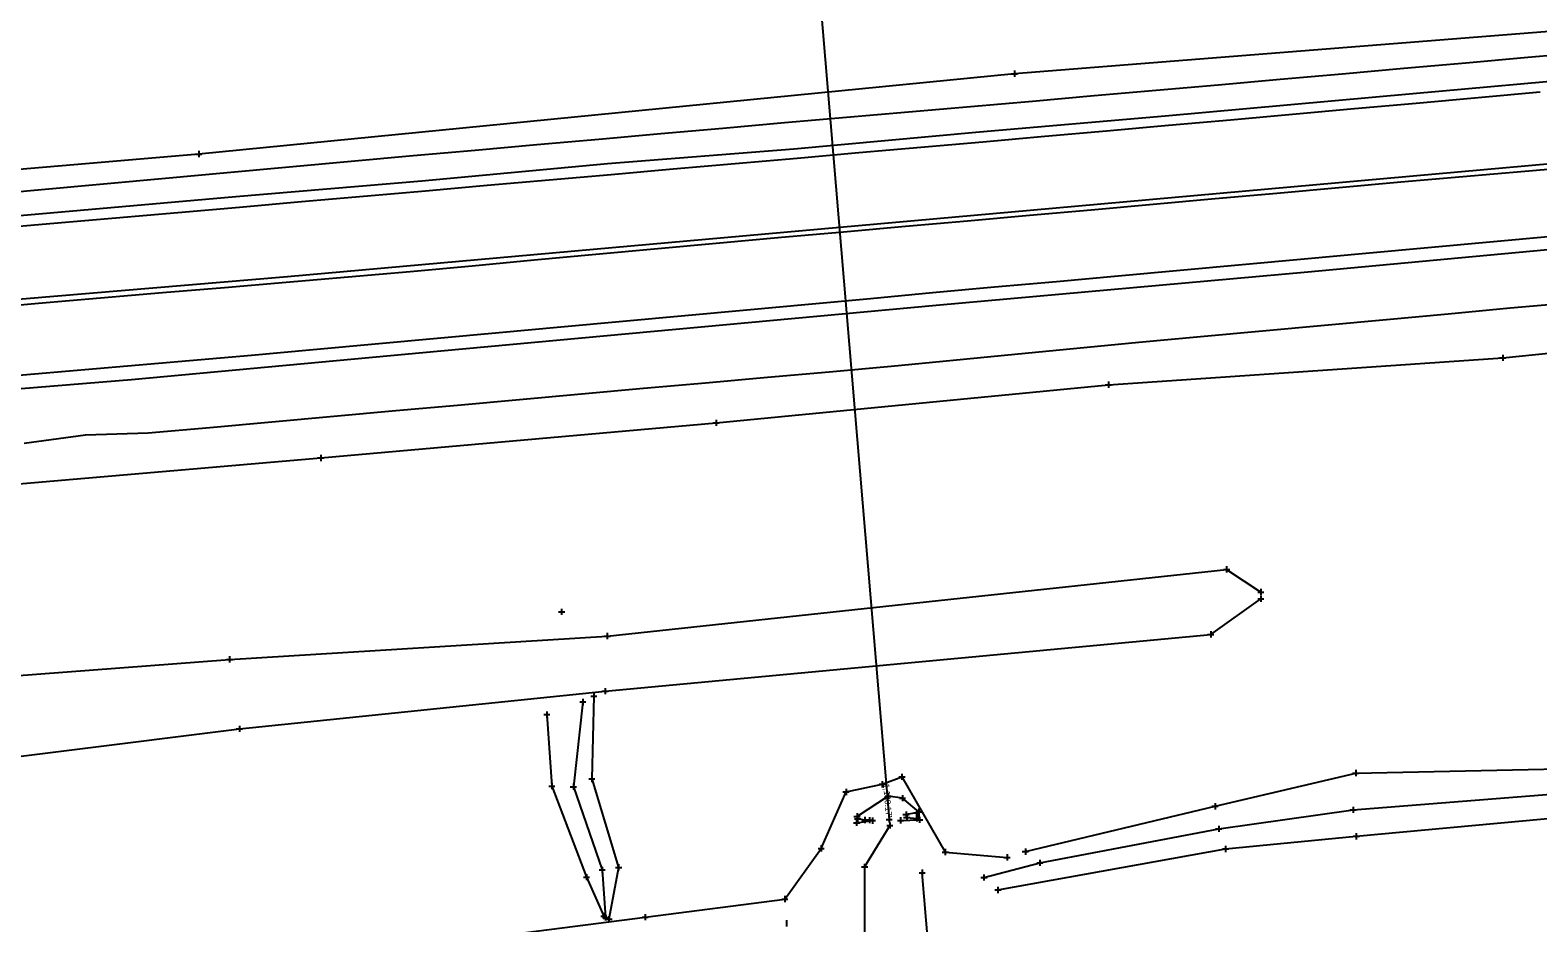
# Model space of a CAD drawing. Extents: x 207090 to 277928, y 600777 to 621109.
# Drawn here: x 261434.3 to 261676.8, y 612064.8 to 612208.4 of the extents above; entities that cross this region are included whole.
import ezdxf

# ---------------------------------------------------------------- set-up
doc = ezdxf.new("R2010")
doc.units = 0
for name, color, linetype in [('ATDIMS', 7, 'Continuous'), ('DR_X_Ditch', 7, 'Continuous'), ('DR_X_Headwall', 7, 'Continuous'), ('DR_X_Storm_Sewer', 7, 'Continuous'), ('HY_X_Water_Edge', 7, 'Continuous'), ('PM_P_Edge_Line', 7, 'Continuous'), ('PM_P_Stop_Line', 7, 'Continuous'), ('PM_X_Edge_Line', 7, 'Continuous'), ('PM_X_Lane_Line', 7, 'Continuous'), ('PV_X_COP', 7, 'Continuous'), ('PV_X_EOP', 7, 'Continuous'), ('PV_X_Shoulder_Rumble_Strip', 7, 'Continuous'), ('SC_ProfileRun2', 7, 'Continuous'), ('SV_X_Break_Lines', 7, 'Continuous'), ('SV_X_Toe_of_Slope', 7, 'Continuous')]:
    doc.layers.add(name, color=color, linetype=linetype)

msp = doc.modelspace()

# ---------------------------------------------------------------- linework, layer by layer
at = {"layer": 'DR_X_Ditch'}
for points in [[(261587.67, 612072.1), (261596.66, 612074.46), (261625.44, 612079.93), (261647.05, 612082.98), (261707.29, 612087.78), (261756.51, 612096.79), (261822.22, 612111.69), (261862.35, 612121.75), (261869.62, 612124.52), (261870.17, 612126.4)], [(261523.17, 612100.35), (261521.64, 612086.71), (261526.27, 612073.31), (261526.81, 612065.66)], [(261572.54, 612080.46), (261568.48, 612073.82)], [(261568.48, 612073.82), (261568.59, 612020.15), (261578.54, 611927.79), (261603.98, 611904.17), (261618.07, 611868.23), (261663.61, 611784.94), (261667.47, 611772.86)]]:
    msp.add_lwpolyline(points, dxfattribs=at)
at = {"layer": 'DR_X_Headwall'}
for points in [[(261575.25, 612081.77), (261576.9, 612081.6), (261576.88, 612082.48), (261575.15, 612082.21)], [(261569.28, 612081.32), (261568.52, 612081.35), (261567.36, 612081.53)]]:
    msp.add_lwpolyline(points, dxfattribs=at)
at = {"layer": 'DR_X_Storm_Sewer'}
msp.add_line((261547.33, 612379.42), (261572.44, 612081.43), dxfattribs=at)
at = {"layer": 'HY_X_Water_Edge'}
msp.add_lwpolyline([(261668.89, 611786.74), (261623.52, 611871.92), (261599.31, 611926.43), (261586.65, 611981.1), (261582.23, 612019.52), (261577.74, 612072.86)], dxfattribs=at)
at = {"layer": 'PM_P_Edge_Line'}
for points in [[(262691.17, 612299.71), (262558.11, 612286.52), (262430.17, 612277.43), (262301.59, 612265.47), (262139.8, 612250.04), (262013.02, 612239.05), (261851.77, 612225.58), (261721.98, 612211.64), (261592.59, 612201.42), (261461.4, 612188.5), (261326.91, 612177), (261204.29, 612172.31), (261203.79, 612197.21), (261194.23, 612211.46)], [(261166.19, 612112.27), (261229.12, 612117.55), (261292.26, 612122.22), (261355.79, 612127.7), (261417.51, 612134.17), (261481.01, 612139.6), (261544.6, 612145.26), (261607.7, 612151.39), (261671.11, 612155.71), (261734.7, 612162.2), (261800.15, 612167.35), (261866.92, 612170.66), (261934.78, 612175.92), (261991.88, 612185.8), (262015.18, 612187.39), (262056.96, 612191.38), (262138.36, 612199.04), (262221.59, 612205.24), (262304.08, 612210.43), (262405.7, 612222.35)], [(261594.35, 612076.26), (261624.84, 612083.55), (261647.48, 612088.9), (261707.89, 612090.17), (261755.27, 612098.62), (261821.94, 612116.68), (261862.35, 612125.03), (261875.37, 612130.72)], [(261589.93, 612070.09), (261626.55, 612076.69), (261647.57, 612078.73), (261708.01, 612084.31), (261757.15, 612093.18), (261825.61, 612102.33), (261823.02, 612108.36), (261863.27, 612119.66), (261875.97, 612119.24), (261875.86, 612129.94)], [(261282.94, 612074.88), (261303.34, 612074.99), (261352, 612080.99), (261411.83, 612088.97), (261467.93, 612096.02), (261526.73, 612102.07), (261624.15, 612111.22), (261632.22, 612116.93)], [(261524.93, 612101.26), (261524.61, 612087.96), (261528.92, 612073.73), (261527.36, 612065.39)], [(261517.37, 612098.3), (261518.17, 612086.81), (261523.75, 612072.15), (261526.54, 612065.89)]]:
    msp.add_lwpolyline(points, dxfattribs=at)
at = {"layer": 'PM_P_Stop_Line'}
for p, q in [((261592.09, 612201.42), (261593.09, 612201.42)), ((261592.59, 612201.92), (261592.59, 612200.92)), ((261592.59, 612201.42), (261592.59, 612201.42)), ((261460.9, 612188.5), (261461.9, 612188.5)), ((261461.4, 612189), (261461.4, 612188)), ((261461.4, 612188.5), (261461.4, 612188.5)), ((261670.61, 612155.71), (261671.61, 612155.71)), ((261671.11, 612156.21), (261671.11, 612155.21)), ((261671.11, 612155.71), (261671.11, 612155.71)), ((261607.2, 612151.39), (261608.2, 612151.39)), ((261607.7, 612151.89), (261607.7, 612150.89)), ((261607.7, 612151.39), (261607.7, 612151.39)), ((261544.1, 612145.26), (261545.1, 612145.26)), ((261544.6, 612145.76), (261544.6, 612144.76)), ((261544.6, 612145.26), (261544.6, 612145.26)), ((261481.01, 612140.1), (261481.01, 612139.1)), ((261480.51, 612139.6), (261481.51, 612139.6)), ((261481.01, 612139.6), (261481.01, 612139.6)), ((261626.21, 612121.67), (261627.21, 612121.67)), ((261626.71, 612122.17), (261626.71, 612121.17)), ((261626.71, 612121.67), (261626.71, 612121.67)), ((261632.21, 612118.52), (261632.21, 612117.52)), ((261631.71, 612118.02), (261632.71, 612118.02)), ((261631.72, 612116.93), (261632.72, 612116.93)), ((261632.21, 612118.02), (261632.21, 612118.02)), ((261632.22, 612117.43), (261632.22, 612116.43)), ((261632.22, 612116.93), (261632.22, 612116.93)), ((261526.59, 612110.95), (261527.59, 612110.95)), ((261527.09, 612111.45), (261527.09, 612110.45)), ((261527.09, 612110.95), (261527.09, 612110.95)), ((261623.65, 612111.22), (261624.65, 612111.22)), ((261624.15, 612111.72), (261624.15, 612110.72)), ((261624.15, 612111.22), (261624.15, 612111.22)), ((261465.85, 612107.2), (261466.85, 612107.2)), ((261466.35, 612107.7), (261466.35, 612106.7)), ((261466.35, 612107.2), (261466.35, 612107.2)), ((261524.43, 612101.26), (261525.43, 612101.26)), ((261524.93, 612101.76), (261524.93, 612100.76)), ((261524.93, 612101.26), (261524.93, 612101.26)), ((261526.23, 612102.07), (261527.23, 612102.07)), ((261526.73, 612102.57), (261526.73, 612101.57)), ((261526.73, 612102.07), (261526.73, 612102.07)), ((261517.37, 612098.8), (261517.37, 612097.8)), ((261522.67, 612100.35), (261523.67, 612100.35)), ((261523.17, 612100.85), (261523.17, 612099.85)), ((261523.17, 612100.35), (261523.17, 612100.35)), ((261467.93, 612096.52), (261467.93, 612095.52)), ((261516.87, 612098.3), (261517.87, 612098.3)), ((261517.37, 612098.3), (261517.37, 612098.3)), ((261467.43, 612096.02), (261468.43, 612096.02)), ((261467.93, 612096.02), (261467.93, 612096.02)), ((261647.48, 612089.4), (261647.48, 612088.4)), ((261517.67, 612086.81), (261518.67, 612086.81)), ((261518.17, 612087.31), (261518.17, 612086.31)), ((261518.17, 612086.81), (261518.17, 612086.81)), ((261521.14, 612086.71), (261522.14, 612086.71)), ((261521.64, 612087.21), (261521.64, 612086.21)), ((261521.64, 612086.71), (261521.64, 612086.71)), ((261524.11, 612087.96), (261525.11, 612087.96)), ((261524.61, 612088.46), (261524.61, 612087.46)), ((261524.61, 612087.96), (261524.61, 612087.96)), ((261570.81, 612087.09), (261571.81, 612087.09)), ((261571.31, 612087.59), (261571.31, 612086.59)), ((261571.31, 612087.09), (261571.31, 612087.09)), ((261573.99, 612088.3), (261574.99, 612088.3)), ((261574.49, 612088.8), (261574.49, 612087.8)), ((261574.49, 612088.3), (261574.49, 612088.3)), ((261646.98, 612088.9), (261647.98, 612088.9)), ((261647.48, 612088.9), (261647.48, 612088.9)), ((261565, 612085.86), (261566, 612085.86)), ((261565.5, 612086.36), (261565.5, 612085.36)), ((261565.5, 612085.86), (261565.5, 612085.86)), ((261571.77, 612085.18), (261572.77, 612085.18)), ((261572.27, 612085.68), (261572.27, 612084.68)), ((261572.27, 612085.18), (261572.27, 612085.18)), ((261574.08, 612084.87), (261575.08, 612084.87)), ((261574.58, 612085.37), (261574.58, 612084.37)), ((261574.58, 612084.87), (261574.58, 612084.87)), ((261566.77, 612081.93), (261567.77, 612081.93)), ((261567.27, 612082.43), (261567.27, 612081.43)), ((261567.27, 612081.93), (261567.27, 612081.93)), ((261567.36, 612082.03), (261567.36, 612081.03)), ((261568.52, 612081.85), (261568.52, 612080.85)), ((261569.28, 612081.82), (261569.28, 612080.82)), ((261574.28, 612081.78), (261574.28, 612080.78)), ((261574.65, 612082.21), (261575.65, 612082.21)), ((261575.15, 612082.71), (261575.15, 612081.71)), ((261575.15, 612082.21), (261575.15, 612082.21)), ((261575.25, 612082.27), (261575.25, 612081.27)), ((261576.38, 612082.48), (261577.38, 612082.48)), ((261576.71, 612082.69), (261577.71, 612082.69)), ((261576.88, 612082.98), (261576.88, 612081.98)), ((261576.88, 612082.48), (261576.88, 612082.48)), ((261576.9, 612082.1), (261576.9, 612081.1)), ((261577.21, 612083.19), (261577.21, 612082.19)), ((261577.21, 612082.69), (261577.21, 612082.69)), ((261577.33, 612081.87), (261577.33, 612080.87)), ((261624.34, 612083.55), (261625.34, 612083.55)), ((261624.84, 612084.05), (261624.84, 612083.05)), ((261624.84, 612083.55), (261624.84, 612083.55)), ((261646.55, 612082.98), (261647.55, 612082.98)), ((261647.05, 612083.48), (261647.05, 612082.48)), ((261647.05, 612082.98), (261647.05, 612082.98)), ((261566.69, 612080.89), (261567.69, 612080.89)), ((261566.86, 612081.53), (261567.86, 612081.53)), ((261567.19, 612081.39), (261567.19, 612080.39)), ((261567.19, 612080.89), (261567.19, 612080.89)), ((261567.36, 612081.53), (261567.36, 612081.53)), ((261568.02, 612081.35), (261569.02, 612081.35)), ((261568.52, 612081.35), (261568.52, 612081.35)), ((261568.78, 612081.32), (261569.78, 612081.32)), ((261569.23, 612081.25), (261570.23, 612081.25)), ((261569.28, 612081.32), (261569.28, 612081.32)), ((261569.73, 612081.75), (261569.73, 612080.75)), ((261569.73, 612081.25), (261569.73, 612081.25)), ((261572.04, 612080.46), (261573.04, 612080.46)), ((261572.54, 612080.96), (261572.54, 612079.96)), ((261572.54, 612080.46), (261572.54, 612080.46)), ((261573.78, 612081.28), (261574.78, 612081.28)), ((261574.28, 612081.28), (261574.28, 612081.28)), ((261574.75, 612081.77), (261575.75, 612081.77)), ((261575.25, 612081.77), (261575.25, 612081.77)), ((261576.4, 612081.6), (261577.4, 612081.6)), ((261576.83, 612081.37), (261577.83, 612081.37)), ((261576.9, 612081.6), (261576.9, 612081.6)), ((261577.33, 612081.37), (261577.33, 612081.37)), ((261624.94, 612079.93), (261625.94, 612079.93)), ((261625.44, 612080.43), (261625.44, 612079.43)), ((261625.44, 612079.93), (261625.44, 612079.93)), ((261561.49, 612077.28), (261561.49, 612076.28)), ((261626.55, 612077.19), (261626.55, 612076.19)), ((261647.07, 612078.73), (261648.07, 612078.73)), ((261647.57, 612079.23), (261647.57, 612078.22)), ((261647.57, 612078.73), (261647.57, 612078.73)), ((261560.99, 612076.78), (261561.99, 612076.78)), ((261561.49, 612076.78), (261561.49, 612076.78)), ((261580.96, 612076.19), (261581.96, 612076.19)), ((261581.46, 612076.69), (261581.46, 612075.69)), ((261581.46, 612076.19), (261581.46, 612076.19)), ((261590.92, 612075.34), (261591.92, 612075.34)), ((261591.42, 612075.84), (261591.42, 612074.84)), ((261591.42, 612075.34), (261591.42, 612075.34)), ((261593.85, 612076.26), (261594.85, 612076.26)), ((261594.35, 612076.76), (261594.35, 612075.76)), ((261594.35, 612076.26), (261594.35, 612076.26)), ((261596.66, 612074.96), (261596.66, 612073.96)), ((261626.05, 612076.69), (261627.05, 612076.69)), ((261626.55, 612076.69), (261626.55, 612076.69)), ((261523.25, 612072.15), (261524.25, 612072.15)), ((261523.75, 612072.65), (261523.75, 612071.65)), ((261523.75, 612072.15), (261523.75, 612072.15)), ((261525.77, 612073.31), (261526.77, 612073.31)), ((261526.27, 612073.81), (261526.27, 612072.81)), ((261526.27, 612073.31), (261526.27, 612073.31)), ((261528.42, 612073.73), (261529.42, 612073.73)), ((261528.92, 612074.23), (261528.92, 612073.23)), ((261528.92, 612073.73), (261528.92, 612073.73)), ((261567.98, 612073.82), (261568.98, 612073.82)), ((261568.48, 612074.32), (261568.48, 612073.32)), ((261568.48, 612073.82), (261568.48, 612073.82)), ((261577.24, 612072.86), (261578.24, 612072.86)), ((261577.74, 612073.36), (261577.74, 612072.36)), ((261577.74, 612072.86), (261577.74, 612072.86)), ((261587.17, 612072.1), (261588.17, 612072.1)), ((261587.67, 612072.6), (261587.67, 612071.6)), ((261587.67, 612072.1), (261587.67, 612072.1)), ((261596.16, 612074.46), (261597.16, 612074.46)), ((261596.66, 612074.46), (261596.66, 612074.46)), ((261589.43, 612070.09), (261590.43, 612070.09)), ((261589.93, 612070.59), (261589.93, 612069.59)), ((261589.93, 612070.09), (261589.93, 612070.09)), ((261555.15, 612068.63), (261556.15, 612068.63)), ((261555.65, 612069.13), (261555.65, 612068.13)), ((261555.65, 612068.63), (261555.65, 612068.63)), ((261526.04, 612065.89), (261527.04, 612065.89)), ((261526.31, 612065.66), (261527.31, 612065.66)), ((261526.54, 612066.39), (261526.54, 612065.39)), ((261526.54, 612065.89), (261526.54, 612065.89)), ((261526.81, 612066.16), (261526.81, 612065.16)), ((261526.81, 612065.66), (261526.81, 612065.66)), ((261526.86, 612065.39), (261527.86, 612065.39)), ((261527.36, 612065.89), (261527.36, 612064.89)), ((261527.36, 612065.39), (261527.36, 612065.39)), ((261532.68, 612065.71), (261533.68, 612065.71)), ((261533.18, 612066.21), (261533.18, 612065.21)), ((261533.18, 612065.71), (261533.18, 612065.71)), ((261555.92, 612065.21), (261555.92, 612064.21))]:
    msp.add_line(p, q, dxfattribs=at)
at = {"layer": 'PM_X_Edge_Line'}
for points in [[(261677.12, 612198.43), (261667.17, 612197.54), (261657.21, 612196.64), (261647.25, 612195.75), (261637.29, 612194.86), (261627.33, 612193.97), (261617.37, 612193.09), (261607.41, 612192.2), (261597.45, 612191.32), (261587.49, 612190.43), (261577.53, 612189.55), (261567.57, 612188.67), (261557.61, 612187.8), (261547.65, 612186.92), (261537.69, 612186.05), (261527.72, 612185.18), (261517.76, 612184.3), (261507.8, 612183.43), (261497.84, 612182.55), (261487.88, 612181.67), (261477.92, 612180.79), (261467.96, 612179.91), (261458, 612179.03), (261448.04, 612178.18), (261438.07, 612177.33), (261428.11, 612176.48)], [(261678.99, 612175.25), (261669.03, 612174.34), (261659.07, 612173.42), (261649.11, 612172.5), (261639.16, 612171.58), (261629.2, 612170.67), (261619.24, 612169.77), (261609.28, 612168.87), (261599.32, 612167.96), (261589.36, 612167.06), (261579.4, 612166.15), (261569.44, 612165.23), (261559.48, 612164.31), (261549.53, 612163.39), (261539.57, 612162.47), (261529.61, 612161.55), (261519.65, 612160.63), (261509.69, 612159.73), (261499.73, 612158.82), (261489.77, 612157.92), (261479.81, 612157.02), (261469.85, 612156.11), (261459.9, 612155.21), (261449.93, 612154.36), (261439.97, 612153.5), (261430, 612152.64)]]:
    msp.add_lwpolyline(points, dxfattribs=at)
at = {"layer": 'PM_X_Lane_Line'}
msp.add_lwpolyline([(260928.82, 612120.67), (261119.02, 612137.73), (261236.66, 612148.16), (261316.3, 612155.14), (261395.97, 612162.08), (261475.64, 612168.8), (261595.13, 612179.46), (261793.67, 612197.27), (261913.19, 612208.3), (262023.27, 612218.46), (262182.04, 612232.94), (262311.42, 612244.99), (262421.66, 612255.04), (262540.53, 612265.71), (262660.66, 612276.53), (262779.48, 612287.4), (262883.05, 612296.85)], dxfattribs=at)
at = {"layer": 'PV_X_COP'}
msp.add_lwpolyline([(261425.65, 612163.62), (261435.62, 612164.48), (261445.58, 612165.34), (261455.54, 612166.2), (261465.51, 612167.05), (261475.47, 612167.91), (261485.43, 612168.76), (261495.39, 612169.62), (261505.35, 612170.54), (261515.31, 612171.46), (261525.26, 612172.38), (261535.22, 612173.29), (261545.18, 612174.21), (261555.14, 612175.11), (261565.1, 612176), (261575.06, 612176.88), (261585.02, 612177.77), (261594.98, 612178.65), (261604.94, 612179.54), (261614.9, 612180.43), (261624.85, 612181.33), (261634.81, 612182.22), (261644.77, 612183.12), (261654.73, 612184.01), (261664.69, 612184.91), (261674.65, 612185.77), (261684.61, 612186.62)], dxfattribs=at)
at = {"layer": 'PV_X_EOP'}
for points in [[(261426.15, 612181.91), (261436.11, 612182.81), (261446.07, 612183.72), (261456.03, 612184.63), (261465.98, 612185.54), (261475.94, 612186.45), (261485.9, 612187.37), (261495.86, 612188.25), (261505.82, 612189.14), (261515.78, 612190.02), (261525.74, 612190.91), (261535.7, 612191.79), (261545.66, 612192.68), (261555.62, 612193.55), (261565.58, 612194.42), (261575.54, 612195.29), (261585.5, 612196.16), (261595.47, 612197.03), (261605.43, 612197.9), (261615.39, 612198.78), (261625.35, 612199.66), (261635.31, 612200.55), (261645.27, 612201.43), (261655.23, 612202.31), (261665.19, 612203.2), (261675.15, 612204.08), (261685.1, 612204.97)], [(261433.3, 612141.98), (261443.2, 612143.32), (261453.23, 612143.66), (261463.19, 612144.52), (261473.15, 612145.42), (261483.11, 612146.32), (261493.07, 612147.22), (261503.03, 612148.12), (261512.99, 612149.03), (261522.95, 612149.92), (261532.91, 612150.81), (261542.87, 612151.69), (261552.84, 612152.58), (261562.8, 612153.47), (261572.76, 612154.38), (261582.71, 612155.34), (261592.66, 612156.3), (261602.62, 612157.26), (261612.57, 612158.22), (261622.53, 612159.16), (261632.49, 612160.07), (261642.45, 612160.99), (261652.4, 612161.9), (261662.36, 612162.81), (261672.32, 612163.73), (261682.28, 612164.63)]]:
    msp.add_lwpolyline(points, dxfattribs=at)
at = {"layer": 'PV_X_Shoulder_Rumble_Strip'}
for points in [[(261165.14, 612127.36), (261181.53, 612128.65), (261251.23, 612135.18), (261321.01, 612141.19), (261390.73, 612147.34), (261450.59, 612152.24), (261500.34, 612156.85), (261580, 612164.2), (261639.79, 612169.55), (261709.46, 612176.03), (261799.14, 612183.95), (261888.75, 612192.3), (261968.37, 612199.76), (262038.07, 612206.21), (262117.73, 612213.53), (262197.43, 612220.64), (262297.03, 612229.66)], [(261686.54, 612200.87), (261656.66, 612198.2), (261616.85, 612194.59), (261586.94, 612192.01), (261557.09, 612189.3), (261527.13, 612186.9), (261497.29, 612184.12), (261467.36, 612181.61), (261437.48, 612178.99), (261407.6, 612176.37), (261377.68, 612173.89), (261337.83, 612170.42), (261307.93, 612167.8), (261278.04, 612165.2), (261248.15, 612162.55), (261208.36, 612158.92), (261178.48, 612156.44), (261166.35, 612155.54)]]:
    msp.add_lwpolyline(points, dxfattribs=at)
at = {"layer": 'SC_ProfileRun2'}
for p, q in [((261519.25, 612114.85), (261520.25, 612114.85)), ((261519.75, 612115.35), (261519.75, 612114.35)), ((261519.75, 612114.85), (261519.75, 612114.85)), ((261572.44, 612081.94), (261572.44, 612080.94)), ((261571.94, 612081.44), (261572.94, 612081.44)), ((261572.44, 612081.44), (261572.44, 612081.44))]:
    msp.add_line(p, q, dxfattribs=at)
at = {"layer": 'SV_X_Break_Lines'}
msp.add_lwpolyline([(261574.28, 612081.28), (261577.33, 612081.37), (261577.21, 612082.69), (261574.58, 612084.87), (261572.27, 612085.18), (261567.27, 612081.93), (261567.19, 612080.89), (261569.73, 612081.25)], dxfattribs=at)
at = {"layer": 'SV_X_Toe_of_Slope'}
for points in [[(261285.32, 612086.65), (261303.83, 612090.75), (261350.07, 612096.95), (261413.39, 612103.17), (261466.35, 612107.2), (261527.09, 612110.95), (261626.71, 612121.67), (261632.21, 612118.02)], [(261115.74, 612095.34), (261121.54, 612079.96), (261127.23, 612060.91), (261146.08, 612051.66), (261180.89, 612045.01), (261182.75, 612058.77), (261184.23, 612060.79), (261185.51, 612060.77), (261186.53, 612058.23), (261195.23, 612052.91), (261209.9, 612048.06), (261250.32, 612041.77), (261308.33, 612042), (261355.63, 612042.8), (261413.81, 612046.32), (261475.61, 612058.3), (261533.18, 612065.71), (261555.65, 612068.63), (261561.49, 612076.78), (261565.5, 612085.86), (261571.31, 612087.09), (261574.49, 612088.3), (261581.46, 612076.19), (261591.42, 612075.34)]]:
    msp.add_lwpolyline(points, dxfattribs=at)

# ---------------------------------------------------------------- texts
at = {"layer": 'ATDIMS'}
msp.add_text("1,130.17'", height=1, rotation=274.8155, dxfattribs=at).set_placement((261571.46, 612087.15))

doc.saveas('drawing.dxf')
